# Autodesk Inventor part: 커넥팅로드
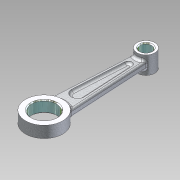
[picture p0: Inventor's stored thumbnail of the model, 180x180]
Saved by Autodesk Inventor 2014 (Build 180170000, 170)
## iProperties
Manager: KYOUNG IL JANG
Company: 한국ATC센터
Created: 2012-10
Part Number: 커넥팅로드
Document SubType Name: Modeling
Density: 1 g/cm^3
Checked By: KYOUNG IL JANG
Vendor: CBT Solutions
Designer: KYOUNG IL JANG
Material: 일반
Appearance: _시험_알루미늄 표면거칠기
Author: KYOUNG IL JANG
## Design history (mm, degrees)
sketch "스케치1"
  geometry: L1 (-19.879, 82.758)-(-19.879, 197.758); L2 (-27.379, 191.144)-(-32.379, 99.633); L3 (-12.379, 191.144)-(-7.379, 99.633); C1 r 14 at (-19.879, 82.758); C2 r 6.5 at (-19.879, 197.758); A1 r 19 centre (-19.879, 82.758) between (-20.11, 101.757) and (-19.649, 63.76) reference; A2 r 21 centre (-19.879, 82.758) between (-32.379, 99.633) and (-7.379, 99.633); A3 r 10 centre (-19.879, 197.758) between (-27.379, 191.144) and (-12.379, 191.144); 1 further point
  constraints: 6 end point, 4 centre point, 4 coincident, 4 point on circle, 2 horizontal alignment, 1 equal length, 1 vertical
  dimensions: "d0" = 28 diameter of C1; "d1" = 42 diameter of A2; "d4" = 115 distance of L1.end C1.centre; "d5" = 20 diameter of A3; "d6" = 13 diameter of C2; "d7" = 25 distance of L3.end L2.end; "d8" = 15 distance of L3.start L2.start
  node "참조1"
extrude "돌출1" new body sketch "스케치1" stored distance "d2" = 13; taper "d3" = 0 deg
extrude "돌출2" join sketch "스케치1" stored distance "d9" = 20; taper "d10" = 0 deg
extrude "돌출3" join sketch "스케치1" stored distance "d11" = 8; taper "d12" = 0 deg
sketch "스케치2"
  geometry: L1 (7.379, 99.633)-(12.379, 191.144) reference; L2 (27.379, 191.144)-(32.379, 99.633) reference; L3 (27.197, 121.158)-(24.092, 177.989); L4 (15.667, 177.989)-(12.561, 121.158); A1 r 21 centre (19.879, 82.758) between (7.379, 99.633) and (32.379, 99.633) reference; A2 r 7.329 centre (19.879, 120.758) between (12.561, 121.158) and (27.197, 121.158); A3 r 4.219 centre (19.879, 177.758) between (24.092, 177.989) and (15.667, 177.989); A4 r 10 centre (19.879, 197.758) between (12.379, 191.144) and (27.379, 191.144) reference; 2 further points
  constraints: 4 end point, 4 point on circle, 4 tangent, 2 centre point, 2 parallel, 1 coincident, 3 other
  dimensions: "d16" = 38 distance of A2.centre A1.centre; "d17" = 4 distance between parallel lines of L2 L3; "d18" = 4 distance between parallel lines of L4 L1; "d25" = 20 distance of A3.centre A4.centre
extrude "돌출4" cut sketch "스케치2" distance "d19" = 5; taper "d20" = 0 deg
fillet "모깎기1" dims "d21" = 2
fillet "모깎기2" dims "d22" = 3
fillet "모깎기3" dims "d23" = 3
chamfer "모따기1" distance "d26" = 1; stored, may be unused: second distance "d27" = 2, angle "d28" = 45 deg
chamfer "모따기2" distance "d29" = 1; stored, may be unused: second distance "d30" = 2, angle "d31" = 45 deg
node "솔리드1"
mirror "대칭1"
other parameters: "d13" = 5, "d14" = 5
